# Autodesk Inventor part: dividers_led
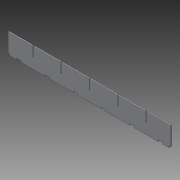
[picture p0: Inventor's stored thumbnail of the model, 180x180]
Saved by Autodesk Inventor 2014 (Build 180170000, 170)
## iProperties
Created: 2014-05
Part Number: dividers_led
Material: ABS Plastic
Document SubType Name: Modeling
Designer: t_emanb
Density: 1 g/cm^3
Appearance: Smooth - White
Author: t_emanb
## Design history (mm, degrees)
sketch "Sketch1"
  geometry: L1 (0, 0)-(584.2, 0); L2 (584.2, 0)-(584.2, 72.39); L3 (584.2, 72.39)-(0, 72.39); L4 (0, 72.39)-(0, 0)
  constraints: 8 end point, 2 parallel, 1 horizontal, 1 perpendicular
  dimensions: "d0" = 584.2 distance of L2.end L3.end; "d1" = 72.39 distance of L3.end L1.start
extrude "Extrusion1" new body sketch "Sketch1" distance "d2" = 3.048; taper "d3" = 0 deg
sketch "Sketch2" dims "d9" = 25.4, "d20" = 25.4, "d32" = 25.4
  geometry: L1 (88.9, 72.39)-(88.9, 0); L2 (190.5, 72.39)-(190.5, 0); L3 (292.1, 72.39)-(292.1, 0); L4 (393.7, 72.39)-(393.7, 0); L5 (495.3, 72.39)-(495.3, 0); L6 (139.7, 72.39)-(139.7, 0); L7 (38.1, 0)-(38.1, 72.39); L8 (241.3, 0)-(241.3, 72.39); L9 (342.9, 72.39)-(342.9, 0); L10 (444.5, 0)-(444.5, 72.39); L11 (546.1, 72.39)-(546.1, 0); L12 (131.762, 0)-(147.638, 0); L13 (147.638, 0)-(147.638, 5.08); L14 (147.638, 5.08)-(131.763, 5.08); L15 (131.763, 5.08)-(131.762, 0); L16 (249.238, 5.08)-(233.363, 5.08); L17 (233.363, 5.08)-(233.363, 0); L18 (233.363, 0)-(249.238, 0); L19 (249.238, 0)-(249.238, 5.08); L20 (350.838, 5.08)-(334.963, 5.08); L21 (334.963, 5.08)-(334.963, 0); L22 (334.963, 0)-(350.838, 0); L23 (350.838, 0)-(350.838, 5.08); L24 (452.438, 5.08)-(436.562, 5.08); L25 (436.562, 5.08)-(436.562, 0); L26 (436.562, 0)-(452.438, 0); L27 (452.438, 0)-(452.438, 5.08); L28 (554.038, 5.08)-(538.162, 5.08); L29 (538.162, 5.08)-(538.162, 0); L30 (538.162, 0)-(554.038, 0); L31 (554.038, 0)-(554.038, 5.08); L32 (30.163, 0)-(46.037, 0); L33 (46.037, 0)-(46.037, 5.08); L34 (46.037, 5.08)-(30.163, 5.08); L35 (30.163, 5.08)-(30.163, 0); L36 (87.376, 72.39)-(90.424, 72.39); L37 (90.424, 72.39)-(90.424, 38.1); L38 (90.424, 38.1)-(87.376, 38.1); L39 (87.376, 38.1)-(87.376, 72.39); L40 (188.976, 38.1)-(188.976, 72.39); L41 (188.976, 72.39)-(192.024, 72.39); L42 (192.024, 72.39)-(192.024, 38.1); L43 (192.024, 38.1)-(188.976, 38.1); L44 (290.576, 38.1)-(290.576, 72.39); L45 (290.576, 72.39)-(293.624, 72.39); L46 (293.624, 72.39)-(293.624, 38.1); L47 (293.624, 38.1)-(290.576, 38.1); L48 (392.176, 38.1)-(392.176, 72.39); L49 (392.176, 72.39)-(395.224, 72.39); L50 (395.224, 72.39)-(395.224, 38.1); L51 (395.224, 38.1)-(392.176, 38.1); L52 (493.776, 38.1)-(493.776, 72.39); L53 (493.776, 72.39)-(496.824, 72.39); L54 (496.824, 72.39)-(496.824, 38.1); L55 (496.824, 38.1)-(493.776, 38.1); 4 further points
  constraints: 110 end point, 40 horizontal alignment, 26 parallel, 16 collinear, 7 vertical, 3 horizontal, 3 perpendicular, 26 other
  dimensions: "d6" = 101.6 distance of L1.start L2.start; "d11" = 50.8 distance between parallel lines of L11 L5; "d12" = 50.8 distance between parallel lines of L1 L7; "d13" = 15.875 distance of L13.end L14.end; "d14" = 5.08 distance of L12.end L13.end; "d17" = 101.6 distance of L13.end L16.start; "d22" = 5.08 distance of L32.end L33.end; "d24" = 3.048 distance of L37.end L38.end; "d25" = 38.1 distance of the line from the sketch origin of L38; "d26" = 1.524 distance between parallel lines of L37 L1 (= 0.5 x d24); "d29" = 101.6 distance of L38.end L40.start; "d42" = 15.875 distance between parallel lines of L35 L33 (= d13)
extrude "Extrusion2" cut sketch "Sketch2" stored distance "d34" = 3.175; taper "d35" = 0 deg
sketch "Sketch3"
  geometry: L1 (554.038, 0)-(584.2, 0) reference; L2 (584.2, 0)-(584.2, 72.39) reference; L3 (0, 72.39)-(0, 0) reference; L4 (0, 0)-(30.163, 0) reference; L5 (538.162, 5.08)-(554.038, 5.08) reference; L6 (0, 6.35)-(6.35, 6.35); L7 (584.2, 6.35)-(577.85, 6.35); L8 (577.85, 6.35)-(577.85, 0); L9 (6.35, 6.35)-(6.35, 0)
  constraints: 8 end point, 4 point on line, 3 perpendicular, 1 parallel
  dimensions: "d36" = 6.35 distance of L7.start L7.end; "d37" = 6.35 distance of L6.start L6.end (= d36); "d38" = 6.35 distance of L7.end L8.end; "d39" = 6.35 distance of L6.end L9.end (= d38)
extrude "Extrusion3" cut sketch "Sketch3" stored distance "d40" = 25.4; taper "d41" = 0 deg
body "Solid1"
